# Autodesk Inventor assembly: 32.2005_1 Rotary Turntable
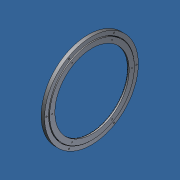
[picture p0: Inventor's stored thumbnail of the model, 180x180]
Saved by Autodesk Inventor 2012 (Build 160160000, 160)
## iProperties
Created: 2017-02
Part Number: 32.2005_1 Rotary Turntable
Document SubType Name: Assembly
Designer: Admin
Author: Admin
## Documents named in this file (3)
- C:\Andys Backup Data\ANDY'S INVENTOR\INVENTOR LIBRARIES\PARTS LIBRARY\INDEXING POSITIONING AND FIXTURING\32.2005_1 Rotary Turntable.iam
- C:\Andys Backup Data\ANDY'S INVENTOR\INVENTOR LIBRARIES\PARTS LIBRARY\INDEXING POSITIONING AND FIXTURING\SUBCOMPONENTS\32.2005_1 ROTARY TURNTABLE INNER RING.ipt
- C:\Andys Backup Data\ANDY'S INVENTOR\INVENTOR LIBRARIES\PARTS LIBRARY\INDEXING POSITIONING AND FIXTURING\SUBCOMPONENTS\32.2005_1 ROARY TURNTABLE OUTER RING.ipt
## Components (2 placed, 2 different names)
1. 32.2005_1 ROTARY TURNTABLE INNER RING:1 — Mate:1, Mate:2
2. 32.2005_1 ROARY TURNTABLE OUTER RING:1 — Mate:1, Mate:2
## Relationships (2: Mate 2)
- Mate:1: 32.2005_1 ROTARY TURNTABLE INNER RING:1 ↔ 32.2005_1 ROARY TURNTABLE OUTER RING:1
- Mate:2: 32.2005_1 ROTARY TURNTABLE INNER RING:1 ↔ 32.2005_1 ROARY TURNTABLE OUTER RING:1
